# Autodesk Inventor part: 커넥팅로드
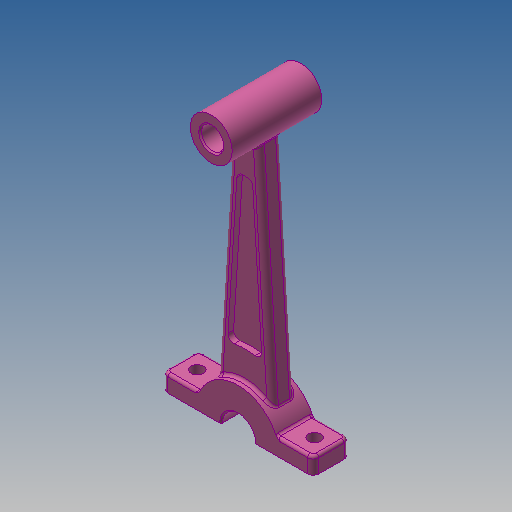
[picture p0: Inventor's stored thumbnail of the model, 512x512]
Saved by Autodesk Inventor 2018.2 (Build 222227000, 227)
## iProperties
Created: 2016-11
Part Number: 커넥팅로드
Material: 알루미늄 6061
Document SubType Name: Modeling
Designer: mduedu
Density: 2.71 g/cm^3
Mass: 44.5487 g
Surface Area: 86.7069 cm^2
Volume: 16.4386 cm^3
Appearance: 분홍색
Author: mduedu
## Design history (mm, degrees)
sketch "스케치1" dims "d0" = 30, "d3" = 15
  geometry: L1 (0, 0)-(0, 96); L2 (-5, 90.41)-(-10, 11.18); L3 (5, 90.41)-(10, 11.18); C1 r 6 at (0, 0); C2 r 4 at (0, 96); 3 further points
  constraints: 6 end point, 4 coincident, 2 centre point, 2 symmetric about line, 1 vertical, 6 other
  dimensions: "d1" = 12 diameter of C1; "d2" = 8 diameter of C2; "d4" = 96 distance of L1.start L1.end; "d6" = 10 distance from line of L1 L2.end; "d7" = 5 distance from line of L1 L2.start
extrude "돌출1" new body sketch "스케치1" stored distance "d8" = 13; taper "d9" = 0 deg
extrude "돌출2" join sketch "스케치1" stored distance "d10" = 32; taper "d11" = 0 deg
sketch "스케치2"
  geometry: L1 (5, 90.41)-(10, 11.18) reference; L2 (-5, 90.41)-(-10, 11.18) reference; A1 r 7.5 centre (0, 96) between (5, 90.41) and (-5, 90.41) reference; A2 r 15 centre (0, 0) between (10, 11.18) and (-10, 11.18) reference
extrude "돌출3" join sketch "스케치2" stored distance "d12" = 8; taper "d13" = 0 deg
sketch "스케치3"
  geometry: L1 (-2.732, 78.715)-(-6.171, 24.226); L2 (2.732, 78.715)-(6.171, 24.226); L3 (0, 78.5)-(0, 25); A1 r 17.5 centre (0, 96) between (-2.732, 78.715) and (2.732, 78.715); A2 r 25 centre (0, 0) between (6.171, 24.226) and (-6.171, 24.226); 9 further points; 2 other entities
  constraints: 6 end point, 6 point on circle, 2 centre point, 1 symmetric about line, 1 vertical alignment, 6 other
  dimensions: "d18" = 10 dimension on A1; "d19" = 10 dimension on A2; "d20" = 3 dimension on L1
extrude "돌출4" cut sketch "스케치3" distance "d21" = 2; taper "d22" = 0 deg
fillet "모깎기1" dims "d23" = 2
fillet "모깎기2" dims "d24" = 2
fillet "모깎기3" dims "d25" = 1
chamfer "모따기1" distance "d26" = 0.5; stored, may be unused: second distance "d27" = 2, angle "d28" = 45 deg
sketch "스케치4"
  geometry: L1 (-27, -6)-(-13.748, -6); L2 (27, -6)-(27, 6); L3 (27, 6)-(13.748, 6); L4 (-27, 6)-(-27, -6); L5 (-27, -6)-(27, 6); L6 (27, -6)-(-27, 6); L7 (-13.748, 6)-(-27, 6); L8 (13.748, 6)-(-13.748, 6); L9 (13.748, -6)-(27, -6); L10 (-13.748, -6)-(13.748, -6); A1 r 15 centre (0, 0) between (-13.748, 6) and (13.748, 6) reference; 1 further point
  constraints: 20 end point, 10 parallel, 4 point on circle, 3 horizontal, 3 perpendicular, 2 midpoint
  dimensions: "d29" = 54 distance of L1.start L2.start; "d31" = 12 distance of L2.start L2.end
extrude "돌출5" join sketch "스케치4" stored distance "d32" = 0; taper "d33" = 0 deg
fillet "모깎기4" dims "d34" = 2
fillet "모깎기5" dims "d35" = 1
fillet "모깎기6" dims "d36" = 1
sketch "스케치5"
  geometry: L1 (1, 0)-(1, 9) reference; L2 (-18.5, 20.5)-(-33.5, 20.5) reference; L3 (-33.5, -11.5)-(-18.5, -11.5) reference; L4 (-26, 20.5)-(-26, -11.5); 3 further points
  constraints: 2 end point, 2 midpoint, 1 horizontal alignment, 1 symmetric about line
  dimensions: "d37" = 6 distance from line of point (-5, 4.5) L1
feature "분할1"
sketch "스케치7"
  geometry: 2 further points
  constraints: 2 other
hole "구멍2" sketch "스케치7" at (-47, 4.5), (-5, 4.5) diameter "d45" = 4.5; stored, may be unused: countersink angle "d49" = 90 deg, drill point angle "d51" = 0 deg; dims "d46" = 6, "d47" = 4, "d48" = 2, "d50" = 8
node "솔리드1"
mirror "대칭1"
other parameters: "d16" = 4, "d17" = 4
